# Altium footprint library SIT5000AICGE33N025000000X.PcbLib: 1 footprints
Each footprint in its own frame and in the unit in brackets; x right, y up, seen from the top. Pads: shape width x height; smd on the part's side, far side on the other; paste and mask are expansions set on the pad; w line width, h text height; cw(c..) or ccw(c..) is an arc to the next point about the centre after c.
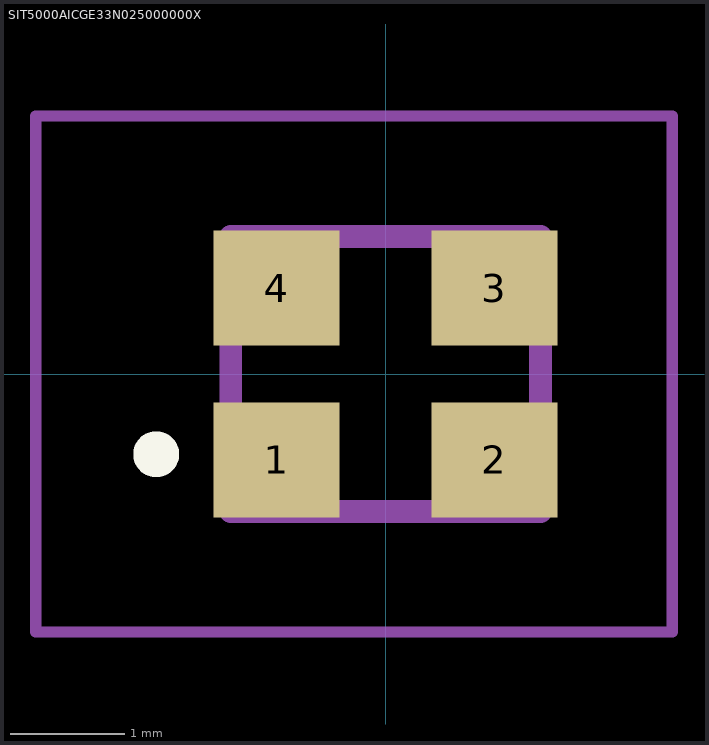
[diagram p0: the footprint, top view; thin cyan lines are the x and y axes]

## SIT5000AICGE33N025000000X [mm]
pads (4):
  rect 1.1x1 smd: 1(-0.95,-0.75) 2(0.95,-0.75) 3(0.95,0.75) 4(-0.95,0.75)
Top Overlay:
  lines w0.2: -2,-0.8 cw(c-2,-0.7) -2,-0.6 ; -2,-0.8 -2,-0.8 ; -2,-0.8 ccw(c-2,-0.7) -2,-0.6 ; -2,-0.6 -2,-0.6
Mechanical 15:
  lines w0.2: -1.35,-1.2 1.35,-1.2 1.35,1.2 -1.35,1.2 -1.35,-1.2
Mechanical 20:
  lines w0.1: -3.05,-2.25 2.5,-2.25 2.5,2.25 -3.05,2.25 -3.05,-2.25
